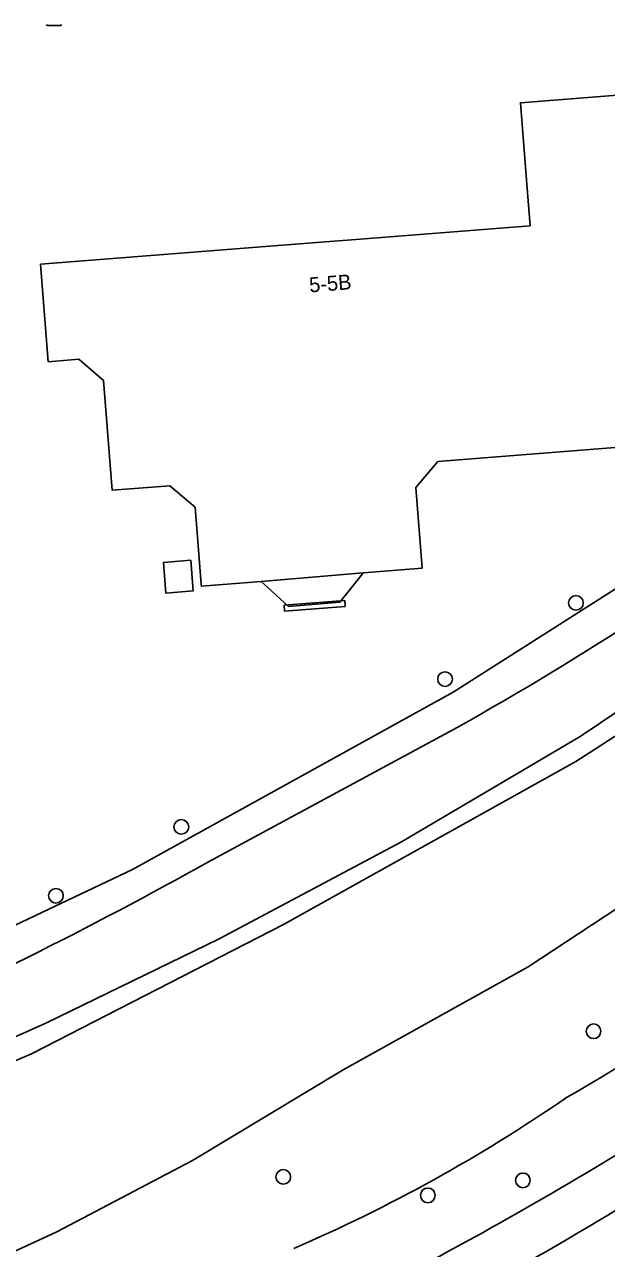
# Model space of a CAD drawing. Extents: x 157793 to 159380, y 380877 to 382313.
# Drawn here: x 158153.9 to 158192.7, y 380941.4 to 381023 of the extents above; entities that cross this region are included whole.
import ezdxf

# ---------------------------------------------------------------- set-up
doc = ezdxf.new("R2010")
doc.units = 0
for name, color, linetype in [('IMGEO_Berm_groen', 7, 'Continuous'), ('IMGEO_Boom', 7, 'Continuous'), ('IMGEO_Erf', 7, 'Continuous'), ('IMGEO_Fietspad_gesloten', 7, 'Continuous'), ('IMGEO_Gemengd_bos', 7, 'Continuous'), ('IMGEO_Groenvoorziening', 7, 'Continuous'), ('IMGEO_Kolk', 7, 'Continuous'), ('IMGEO_Oever', 7, 'Continuous'), ('IMGEO_Pand', 7, 'Continuous'), ('IMGEO_Pand_nummerreeks', 7, 'Continuous'), ('IMGEO_Pand_overbouw', 7, 'Continuous'), ('IMGEO_Waterloop', 7, 'Continuous')]:
    doc.layers.add(name, color=color, linetype=linetype)

msp = doc.modelspace()

# ---------------------------------------------------------------- linework, layer by layer
at = {"layer": 'IMGEO_Berm_groen'}
for centre, radius, start, end in [((158064.541, 381166.888), 249.294, 300.2177, 305.3121), ((158129.165, 381039.961), 107.39, 293.41087, 304.50971), ((158052.096, 381180.521), 272.351, 297.96988, 302.38496), ((158024.617, 381223.74), 326.694, 298.51492, 301.9525)]:
    msp.add_arc(centre, radius, start, end, dxfattribs=at)
at = {"layer": 'IMGEO_Boom'}
for centre in [(158190.636, 380984.437), (158181.908, 380979.357), (158164.332, 380969.511), (158155.973, 380964.919), (158191.806, 380955.886), (158171.125, 380946.186), (158187.096, 380945.949), (158180.761, 380944.953)]:
    msp.add_circle(centre, 0.489, dxfattribs=at)
at = {"layer": 'IMGEO_Erf'}
for points in [[(158054.334, 381160.498), (158058.211, 381110.918), (158062.007, 381064.14), (158062.715, 381051.624), (158064.284, 381030.813), (158074.504, 381031.623), (158077.214, 380962.655), (158077.724, 380949.689), (158117.15, 380951.417), (158135.704, 380956.312), (158141.985, 380957.622), (158161.083, 380966.67), (158182.451, 380978.491), (158196.616, 380987.508)], [(158196.335, 380995.042), (158181.438, 380993.864), (158179.958, 380992.13), (158180.383, 380986.755), (158176.463, 380986.446), (158169.646, 380985.863), (158165.666, 380985.549), (158165.656, 380985.676), (158165.25, 380990.811), (158163.565, 380992.249), (158159.726, 380991.945), (158159.147, 380999.266), (158158.292, 381000), (158157.511, 381000.67), (158155.459, 381000.509), (158154.948, 381007.004), (158173.351, 381008.451), (158176.248, 381008.679), (158187.581, 381009.57), (158187.361, 381012.345), (158186.932, 381017.77), (158212.458, 381019.789)]]:
    msp.add_lwpolyline(points, dxfattribs=at)
for points in [[(158164.957, 380987.275), (158165.117, 380985.241), (158163.293, 380985.087), (158163.133, 380987.12)], [(158175.22, 380984.596), (158175.251, 380984.206), (158171.213, 380983.887), (158171.182, 380984.276)]]:
    msp.add_lwpolyline(points, close=True, dxfattribs=at)
at = {"layer": 'IMGEO_Fietspad_gesloten'}
for centre, radius, start, end in [((158052.096, 381180.521), 272.351, 297.96988, 302.38496), ((158024.617, 381223.74), 326.694, 298.51492, 301.9525)]:
    msp.add_arc(centre, radius, start, end, dxfattribs=at)
at = {"layer": 'IMGEO_Gemengd_bos'}
for points in [[(158196.616, 380987.508), (158182.451, 380978.491), (158161.083, 380966.67), (158141.985, 380957.622), (158135.704, 380956.312), (158117.15, 380951.417), (158077.724, 380949.689), (158077.764, 380948.666), (158076.593, 380948.538), (158068.919, 380946.729), (158066.371, 380945.407), (158060.189, 380944.432), (158062.114, 380943.437), (158067.223, 380944.211), (158078.891, 380946.713), (158102.866, 380947.897), (158115.376, 380948.812)], [(158166.144, 380967.177), (158182.724, 380976.142)]]:
    msp.add_lwpolyline(points, dxfattribs=at)
for centre, radius, start, end in [((158078.682, 381161.902), 212.912, 299.25259, 307.03035), ((158017.178, 381234.778), 306.27, 293.99654, 299.10351)]:
    msp.add_arc(centre, radius, start, end, dxfattribs=at)
at = {"layer": 'IMGEO_Groenvoorziening'}
for points in [[(158115.376, 380948.812), (158102.866, 380947.897), (158078.891, 380946.713), (158067.223, 380944.211), (158062.114, 380943.437), (158069.669, 380940.286), (158070.304, 380940.55), (158073.771, 380940.978), (158077.4, 380941.407), (158087.965, 380943.153), (158111.887, 380944.307), (158116.448, 380944.635), (158119.398, 380945.055), (158142.751, 380951.274), (158148.616, 380953.456), (158155.302, 380956.432), (158166.85, 380962.06), (158179.004, 380968.512), (158190.917, 380975.525), (158203.316, 380983.871), (158212.491, 380990.777), (158223.407, 381000.213), (158236.933, 381012.36)], [(158182.724, 380976.142), (158166.144, 380967.177)]]:
    msp.add_lwpolyline(points, dxfattribs=at)
for centre, radius, start, end in [((158078.682, 381161.902), 212.912, 299.25259, 307.03035), ((158017.178, 381234.778), 306.27, 293.99654, 299.10351)]:
    msp.add_arc(centre, radius, start, end, dxfattribs=at)
at = {"layer": 'IMGEO_Kolk'}
msp.add_line((158156.278, 381022.911), (158155.426, 381022.911), dxfattribs=at)
msp.add_lwpolyline([(158156.278, 381022.911), (158155.426, 381022.911)], dxfattribs=at)
for centre, start, end in [((158155.428, 381022.987), 181.55205, 268.44795), ((158155.428, 381022.987), 181.55205, 268.44795), ((158156.276, 381022.987), 271.55205, 358.44795), ((158156.276, 381022.987), 271.55205, 358.44795)]:
    msp.add_arc(centre, 0.0765, start, end, dxfattribs=at)
at = {"layer": 'IMGEO_Oever'}
for points in [[(158149.694, 380952.409), (158154.346, 380954.381), (158171.137, 380963.007), (158190.634, 380973.857), (158199.847, 380979.797), (158208.499, 380986.232), (158215.648, 380991.572), (158219.625, 380995.025), (158229.749, 381004.027), (158250.954, 381022.323), (158261.03, 381028.554)], [(158268.627, 381025.096), (158256.43, 381014.389), (158246.448, 381005.529), (158239.068, 380999.395), (158233.19, 380995.185), (158229.624, 380992.227), (158225.123, 380987.749), (158215.657, 380980.087), (158205.084, 380972.073), (158196.806, 380966.327), (158187.458, 380960.192), (158175.125, 380953.328), (158165.082, 380947.267), (158155.995, 380942.493), (158147.67, 380938.685)], [(158250.077, 381023.586), (158243.378, 381018.052), (158236.933, 381012.36), (158223.407, 381000.213), (158212.491, 380990.777), (158203.316, 380983.871), (158190.917, 380975.525), (158179.004, 380968.512), (158166.85, 380962.06), (158155.302, 380956.432), (158148.616, 380953.456)]]:
    msp.add_lwpolyline(points, dxfattribs=at)
for centre, radius, start, end in [((158064.541, 381166.888), 249.294, 300.2177, 305.3121), ((158129.165, 381039.961), 107.39, 293.41087, 304.50971)]:
    msp.add_arc(centre, radius, start, end, dxfattribs=at)
at = {"layer": 'IMGEO_Pand'}
msp.add_lwpolyline([(158212.458, 381019.789), (158186.932, 381017.77), (158187.361, 381012.345), (158187.581, 381009.57), (158176.248, 381008.679), (158173.351, 381008.451), (158154.948, 381007.004), (158155.459, 381000.509), (158157.511, 381000.67), (158158.292, 381000), (158159.147, 380999.266), (158159.726, 380991.945), (158163.565, 380992.249), (158165.25, 380990.811), (158165.656, 380985.676), (158165.666, 380985.549), (158169.646, 380985.863), (158176.463, 380986.446), (158180.383, 380986.755), (158179.958, 380992.13), (158181.438, 380993.864), (158196.335, 380995.042)], dxfattribs=at)
for points in [[(158164.957, 380987.275), (158163.133, 380987.12), (158163.293, 380985.087), (158165.117, 380985.241)], [(158175.22, 380984.596), (158171.182, 380984.276), (158171.213, 380983.887), (158175.251, 380984.206)]]:
    msp.add_lwpolyline(points, close=True, dxfattribs=at)
at = {"layer": 'IMGEO_Pand_overbouw'}
msp.add_lwpolyline([(158176.06, 380985.936), (158176.227, 380986.146), (158176.463, 380986.446), (158169.646, 380985.863), (158169.887, 380985.644), (158170.113, 380985.438), (158171.472, 380984.203), (158174.907, 380984.475)], close=True, dxfattribs=at)
at = {"layer": 'IMGEO_Waterloop'}
for points in [[(158261.03, 381028.554), (158250.954, 381022.323), (158229.749, 381004.027), (158219.625, 380995.025), (158215.648, 380991.572), (158208.499, 380986.232), (158199.847, 380979.797), (158190.634, 380973.857), (158171.137, 380963.007), (158154.346, 380954.381), (158149.694, 380952.409)], [(158147.67, 380938.685), (158155.995, 380942.493), (158165.082, 380947.267), (158175.125, 380953.328), (158187.458, 380960.192), (158196.806, 380966.327), (158205.084, 380972.073), (158215.657, 380980.087), (158225.123, 380987.749), (158229.624, 380992.227), (158233.19, 380995.185), (158239.068, 380999.395), (158246.448, 381005.529), (158256.43, 381014.389), (158268.627, 381025.096)]]:
    msp.add_lwpolyline(points, dxfattribs=at)

# ---------------------------------------------------------------- texts
at = {"layer": 'IMGEO_Pand_nummerreeks'}
msp.add_text('5-5B', height=1, rotation=4.49772, dxfattribs=at).set_placement((158172.889, 381005.125))

doc.saveas('drawing.dxf')
